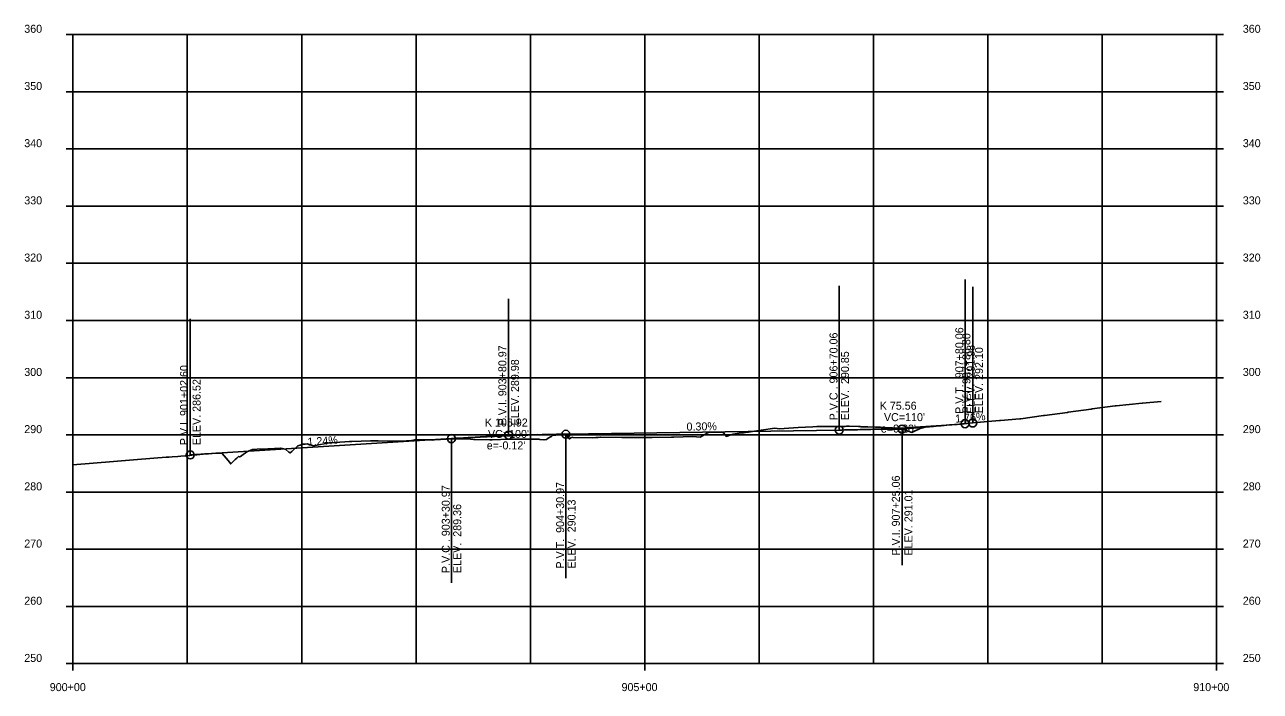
# Model space of a CAD drawing. Extents: x 1300404 to 1323571, y 234004 to 252077.
# Drawn here: x 1320996 to 1322076, y 238061 to 238644 of the extents above; entities that cross this region are included whole.
import ezdxf

# ---------------------------------------------------------------- set-up
doc = ezdxf.new("R2010")
doc.units = 0
for name, color, linetype in [('Default', 7, 'Continuous'), ('R_Axis', 7, 'Continuous'), ('R_Axis Annot', 7, 'Continuous'), ('R_Exist Surface', 7, 'Continuous'), ('R_Grid', 7, 'Continuous'), ('R_Vert Alg', 7, 'Continuous'), ('R_Vert Alg Annot', 7, 'Continuous')]:
    doc.layers.add(name, color=color, linetype=linetype)

msp = doc.modelspace()

# ---------------------------------------------------------------- linework, layer by layer
at = {"layer": 'R_Axis'}
for p, q in [((1321032.1, 238635.3), (1321038.1, 238635.3)), ((1321032.1, 238635.3), (1321038.1, 238635.3)), ((1321038.1, 238085.3), (1321038.1, 238635.3)), ((1322038.1, 238085.3), (1322038.1, 238635.3)), ((1322044.1, 238635.3), (1322038.1, 238635.3)), ((1322044.1, 238635.3), (1322038.1, 238635.3)), ((1321032.1, 238585.3), (1321038.1, 238585.3)), ((1322044.1, 238585.3), (1322038.1, 238585.3)), ((1321032.1, 238535.3), (1321038.1, 238535.3)), ((1322044.1, 238535.3), (1322038.1, 238535.3)), ((1321032.1, 238485.3), (1321038.1, 238485.3)), ((1322044.1, 238485.3), (1322038.1, 238485.3)), ((1321032.1, 238435.3), (1321038.1, 238435.3)), ((1322044.1, 238435.3), (1322038.1, 238435.3)), ((1321032.1, 238385.3), (1321038.1, 238385.3)), ((1322044.1, 238385.3), (1322038.1, 238385.3)), ((1321032.1, 238335.3), (1321038.1, 238335.3)), ((1322044.1, 238335.3), (1322038.1, 238335.3)), ((1321032.1, 238285.3), (1321038.1, 238285.3)), ((1322044.1, 238285.3), (1322038.1, 238285.3)), ((1321032.1, 238235.3), (1321038.1, 238235.3)), ((1322044.1, 238235.3), (1322038.1, 238235.3)), ((1321032.1, 238185.3), (1321038.1, 238185.3)), ((1322044.1, 238185.3), (1322038.1, 238185.3)), ((1321032.1, 238135.3), (1321038.1, 238135.3)), ((1322044.1, 238135.3), (1322038.1, 238135.3)), ((1321032.1, 238085.3), (1321038.1, 238085.3)), ((1321038.1, 238085.3), (1322038.1, 238085.3)), ((1321038.1, 238079.3), (1321038.1, 238085.3)), ((1321538.1, 238079.3), (1321538.1, 238085.3)), ((1322044.1, 238085.3), (1322038.1, 238085.3)), ((1322038.1, 238079.3), (1322038.1, 238085.3))]:
    msp.add_line(p, q, dxfattribs=at)
at = {"layer": 'R_Exist Surface'}
msp.add_lwpolyline([(1321038.1, 238259.2), (1321055.8, 238260.6), (1321073.4, 238262.1), (1321091.1, 238263.5), (1321108.7, 238265), (1321119.5, 238265.7), (1321119.8, 238265.7), (1321121.8, 238265.9), (1321124.8, 238266.1), (1321124.8, 238266.1), (1321124.8, 238266.1), (1321129.8, 238266.4), (1321129.9, 238266.4), (1321132.4, 238266.6), (1321132.4, 238266.6), (1321132.5, 238266.6), (1321136.1, 238266.9), (1321136.3, 238266.9), (1321136.3, 238266.9), (1321139.8, 238267.3), (1321140.1, 238267.3), (1321140.4, 238267.3), (1321142.1, 238267.5), (1321145.4, 238267.8), (1321146.4, 238267.9), (1321147.9, 238268.1), (1321148.9, 238268.2), (1321150.9, 238268.4), (1321150.9, 238268.4), (1321151.9, 238268.5), (1321153.5, 238268.6), (1321156.2, 238268.8), (1321156.7, 238268.8), (1321163.1, 238269.2), (1321165.5, 238269.3), (1321168.3, 238269.3), (1321168.5, 238269.3), (1321168.5, 238269.3), (1321168.6, 238269.1), (1321173.7, 238262.8), (1321176, 238259.9), (1321180, 238263.7), (1321181.4, 238264.8), (1321182.9, 238266.5), (1321183.8, 238266.1), (1321184.5, 238266.5), (1321190.1, 238270.4), (1321193.5, 238271.9), (1321194.6, 238272.3), (1321195.2, 238272.5), (1321196.1, 238272.6), (1321199.3, 238272.9), (1321208.4, 238273.2), (1321209.2, 238273.2), (1321219.2, 238273.7), (1321219.3, 238273.7), (1321219.3, 238273.7), (1321221.4, 238273.3), (1321223.7, 238272.7), (1321224.2, 238272.5), (1321226.8, 238270.2), (1321228, 238269.6), (1321229.6, 238270.9), (1321234.7, 238275.7), (1321236.7, 238276.2), (1321238.3, 238276.9), (1321239.1, 238277.3), (1321241.2, 238277.3), (1321242.8, 238277.4), (1321248.5, 238275.7), (1321251.6, 238276.4), (1321252.9, 238276.7), (1321259.6, 238277.9), (1321261.8, 238278.2), (1321264.1, 238278.3), (1321267.4, 238278.6), (1321279.8, 238279.6), (1321281.5, 238279.6), (1321282, 238279.6), (1321298.4, 238280), (1321304.5, 238280), (1321305, 238280), (1321323.2, 238279.7), (1321325.4, 238279.8), (1321334.1, 238280.3), (1321334.4, 238280.4), (1321337, 238281), (1321346.9, 238280.9), (1321347.5, 238280.9), (1321347.5, 238280.9), (1321347.6, 238280.9), (1321348, 238280.9), (1321350.7, 238281), (1321352.1, 238280.8), (1321353.4, 238280.9), (1321354.3, 238281.1), (1321370, 238281.9), (1321375.2, 238281.8), (1321385.7, 238281.5), (1321388.4, 238281.2), (1321389.9, 238281.4), (1321402.7, 238281.1), (1321403.2, 238281.1), (1321403.8, 238281.1), (1321404.6, 238281), (1321419.6, 238281.6), (1321421.7, 238281.6), (1321433.5, 238281.6), (1321433.8, 238281.6), (1321445.5, 238281.6), (1321446.4, 238281.4), (1321450, 238280.9), (1321452.3, 238281.3), (1321453.6, 238282.5), (1321455.6, 238283.7), (1321456.1, 238283.7), (1321456.3, 238283.7), (1321457.3, 238284.8), (1321466.2, 238285.5), (1321469.8, 238285.4), (1321470.9, 238283.7), (1321472.3, 238281.7), (1321473.5, 238282.7), (1321475.3, 238283.2), (1321475.5, 238283.1), (1321475.6, 238283.1), (1321492.7, 238282.8), (1321495.2, 238283), (1321497.3, 238282.9), (1321499.4, 238283.3), (1321518.1, 238283.1), (1321520.5, 238283.1), (1321522.8, 238283.1), (1321542, 238282.9), (1321544.5, 238283), (1321561.4, 238283.3), (1321563.5, 238283.4), (1321579.9, 238283.8), (1321583.3, 238283.7), (1321586.7, 238283.4), (1321592.6, 238286.7), (1321593.1, 238287.1), (1321594.1, 238287.5), (1321594.1, 238287.4), (1321594.5, 238287.6), (1321595.7, 238287.6), (1321606.5, 238287.5), (1321607, 238287.1), (1321609.6, 238283.9), (1321613.1, 238285.2), (1321615.4, 238286), (1321620.6, 238286.8), (1321622.3, 238287), (1321624.4, 238287.2), (1321626.1, 238287.4), (1321628.9, 238287.7), (1321634, 238288.4), (1321649.9, 238290.9), (1321651.8, 238291.2), (1321655.9, 238290.7), (1321668.2, 238291.4), (1321672.4, 238291.7), (1321685.1, 238292.4), (1321688.7, 238292.7), (1321699.7, 238292.6), (1321709, 238292.6), (1321711.1, 238292.7), (1321713.3, 238292.7), (1321714.7, 238293), (1321717, 238292.9), (1321725.1, 238292.6), (1321726.8, 238292.6), (1321727.2, 238292.4), (1321729.2, 238292.4), (1321733.1, 238292.2), (1321739.9, 238292), (1321741.2, 238291.9), (1321744.2, 238291.9), (1321746.8, 238291.8), (1321749.2, 238291.6), (1321753, 238291.5), (1321757.2, 238291.3), (1321761.7, 238291.2), (1321762.1, 238291), (1321762.7, 238290.9), (1321765.3, 238289.8), (1321771.8, 238287.4), (1321773.3, 238288.2), (1321779.1, 238290.9), (1321781.3, 238291.5), (1321781.4, 238291.6), (1321783.5, 238292.2), (1321784.7, 238292.3), (1321785, 238292.3), (1321787.9, 238292.6), (1321788.7, 238292.6), (1321789.4, 238292.7), (1321793, 238293), (1321796.2, 238293.2), (1321797.4, 238293.3), (1321801.7, 238293.7), (1321805.5, 238294), (1321813.5, 238294.7), (1321814.2, 238294.8), (1321814.8, 238294.8), (1321820.1, 238295.3), (1321821.6, 238295.4), (1321831.3, 238296.3), (1321831.6, 238296.3), (1321848.4, 238297.8), (1321848.8, 238297.8), (1321849.3, 238297.9), (1321866.1, 238299.3), (1321866.9, 238299.4), (1321886.9, 238302.2), (1321887.7, 238302.3), (1321907.8, 238305), (1321908.5, 238305.1), (1321928.6, 238307.9), (1321929.4, 238308), (1321949.5, 238310.8), (1321950.3, 238310.8), (1321973.1, 238313), (1321973.4, 238313.1), (1321989.7, 238314.6)], dxfattribs=at)
at = {"layer": 'R_Grid'}
for p, q in [((1321038.1, 238635.3), (1322038.1, 238635.3)), ((1321038.1, 238635.3), (1322038.1, 238635.3)), ((1321138.1, 238085.3), (1321138.1, 238635.3)), ((1321238.1, 238085.3), (1321238.1, 238635.3)), ((1321338.1, 238085.3), (1321338.1, 238635.3)), ((1321438.1, 238085.3), (1321438.1, 238635.3)), ((1321538.1, 238085.3), (1321538.1, 238635.3)), ((1321638.1, 238085.3), (1321638.1, 238635.3)), ((1321738.1, 238085.3), (1321738.1, 238635.3)), ((1321838.1, 238085.3), (1321838.1, 238635.3)), ((1321938.1, 238085.3), (1321938.1, 238635.3)), ((1321038.1, 238585.3), (1322038.1, 238585.3)), ((1321038.1, 238535.3), (1322038.1, 238535.3)), ((1321038.1, 238485.3), (1322038.1, 238485.3)), ((1321038.1, 238435.3), (1322038.1, 238435.3)), ((1321038.1, 238385.3), (1322038.1, 238385.3)), ((1321038.1, 238335.3), (1322038.1, 238335.3)), ((1321038.1, 238285.3), (1322038.1, 238285.3)), ((1321038.1, 238235.3), (1322038.1, 238235.3)), ((1321038.1, 238185.3), (1322038.1, 238185.3)), ((1321038.1, 238135.3), (1322038.1, 238135.3))]:
    msp.add_line(p, q, dxfattribs=at)
at = {"layer": 'R_Vert Alg'}
for p, q in [((1321708.2, 238289.5), (1321708.2, 238415.5)), ((1321818.2, 238295.1), (1321818.2, 238421.1)), ((1321824.9, 238295.7), (1321824.9, 238414.7)), ((1321419.1, 238285.1), (1321419.1, 238404.1)), ((1321140.7, 238267.8), (1321140.7, 238386.8)), ((1321818.2, 238295.1), (1321824.9, 238295.7)), ((1321394.1, 238283.6), (1321419.1, 238285.1)), ((1321419.1, 238285.1), (1321444.1, 238285.5)), ((1321469.1, 238285.9), (1321708.2, 238289.5)), ((1321469.1, 238285.9), (1321469.1, 238159.9)), ((1321735.7, 238289.9), (1321763.2, 238290.3)), ((1321763.2, 238290.3), (1321790.7, 238292.7)), ((1321763.2, 238290.3), (1321763.2, 238171.3)), ((1321140.7, 238267.8), (1321369.1, 238282)), ((1321369.1, 238282), (1321369.1, 238156))]:
    msp.add_line(p, q, dxfattribs=at)
for points in [[(1321369.1, 238282), (1321371.2, 238282.2), (1321373.3, 238282.3), (1321375.4, 238282.4), (1321377.4, 238282.5), (1321379.5, 238282.7), (1321381.6, 238282.8), (1321383.7, 238282.9), (1321385.8, 238283), (1321387.9, 238283.1), (1321389.9, 238283.2), (1321392, 238283.3), (1321394.1, 238283.4), (1321396.2, 238283.5), (1321398.3, 238283.6), (1321400.4, 238283.7), (1321402.4, 238283.8), (1321404.5, 238283.9), (1321406.6, 238284), (1321408.7, 238284.1), (1321410.8, 238284.2), (1321412.9, 238284.3), (1321414.9, 238284.4), (1321417, 238284.5), (1321421.2, 238284.6), (1321423.3, 238284.7), (1321425.4, 238284.8), (1321427.4, 238284.9), (1321429.5, 238284.9), (1321431.6, 238285), (1321433.7, 238285.1), (1321435.8, 238285.1), (1321437.9, 238285.2), (1321439.9, 238285.3), (1321442, 238285.3), (1321444.1, 238285.4), (1321446.2, 238285.4), (1321448.3, 238285.5), (1321450.4, 238285.5), (1321452.4, 238285.6), (1321454.5, 238285.6), (1321456.6, 238285.7), (1321458.7, 238285.7), (1321460.8, 238285.8), (1321462.9, 238285.8), (1321464.9, 238285.8), (1321467, 238285.9), (1321469.1, 238285.9)], [(1321708.2, 238289.5), (1321710.5, 238289.5), (1321712.8, 238289.6), (1321715.1, 238289.6), (1321717.4, 238289.6), (1321719.7, 238289.7), (1321722, 238289.7), (1321724.2, 238289.8), (1321726.5, 238289.9), (1321728.8, 238289.9), (1321731.1, 238290), (1321733.4, 238290.1), (1321735.7, 238290.1), (1321738, 238290.2), (1321740.3, 238290.3), (1321742.6, 238290.4), (1321744.9, 238290.5), (1321747.2, 238290.6), (1321749.5, 238290.7), (1321751.7, 238290.8), (1321754, 238290.9), (1321756.3, 238291), (1321758.6, 238291.1), (1321760.9, 238291.2), (1321765.5, 238291.4), (1321767.8, 238291.5), (1321770.1, 238291.7), (1321772.4, 238291.8), (1321774.7, 238291.9), (1321777, 238292.1), (1321779.2, 238292.2), (1321781.5, 238292.4), (1321783.8, 238292.5), (1321786.1, 238292.7), (1321788.4, 238292.8), (1321790.7, 238293), (1321793, 238293.1), (1321795.3, 238293.3), (1321797.6, 238293.5), (1321799.9, 238293.6), (1321802.2, 238293.8), (1321804.5, 238294), (1321806.7, 238294.2), (1321809, 238294.4), (1321811.3, 238294.5), (1321813.6, 238294.7), (1321815.9, 238294.9), (1321818.2, 238295.1)]]:
    msp.add_lwpolyline(points, dxfattribs=at)
for centre in [(1321818.2, 238295.1), (1321824.9, 238295.7), (1321369.1, 238282), (1321419.1, 238285.1), (1321469.1, 238285.9), (1321708.2, 238289.5), (1321763.2, 238290.3), (1321140.7, 238267.8)]:
    msp.add_circle(centre, 3.5, dxfattribs=at)

# ---------------------------------------------------------------- texts
at = {"layer": 'Default'}
msp.add_text('-', height=0.0001, dxfattribs=at).set_placement((1321038.1, 238085.3))
at = {"layer": 'R_Axis Annot'}
for s, p in [('360', (1320995.5, 238636.8)), ('360', (1320995.5, 238636.8)), ('360', (1322061.1, 238636.8)), ('360', (1322061.1, 238636.8)), ('350', (1320995.5, 238586.8)), ('350', (1322061.1, 238586.8)), ('340', (1320995.5, 238536.8)), ('340', (1322061.1, 238536.8)), ('330', (1320995.5, 238486.8)), ('330', (1322061.1, 238486.8)), ('320', (1320995.5, 238436.8)), ('320', (1322061.1, 238436.8)), ('310', (1320995.5, 238386.8)), ('310', (1322061.1, 238386.8)), ('300', (1320995.5, 238336.8)), ('300', (1322061.1, 238336.8)), ('290', (1320995.5, 238286.8)), ('290', (1322061.1, 238286.8)), ('280', (1320995.5, 238236.8)), ('280', (1322061.1, 238236.8)), ('270', (1320995.5, 238186.8)), ('270', (1322061.1, 238186.8)), ('260', (1320995.5, 238136.8)), ('260', (1322061.1, 238136.8)), ('250', (1320995.5, 238086.8)), ('250', (1322061.1, 238086.8)), ('900+00', (1321017.8, 238061.3)), ('905+00', (1321517.8, 238061.3)), ('910+00', (1322017.8, 238061.3))]:
    msp.add_text(s, height=7, dxfattribs=at).set_placement(p)
at = {"layer": 'R_Vert Alg Annot'}
for s, rotation, p in [('P.V.C . 906+70.06', 90, (1321706.7, 238298)), ('P.V.T.  907+80.06', 90, (1321816.7, 238303.6)), ('P.V.I. 907+86.80', 90, (1321822.9, 238304.2)), ('P.V.I. 903+80.97', 90, (1321417.1, 238293.6)), ('ELEV.  291.98', 90, (1321826.7, 238303.6)), ('ELEV. 292.10', 90, (1321833.9, 238304.2)), ('ELEV. 289.98', 90, (1321428.1, 238293.6)), ('ELEV.  290.85', 90, (1321716.7, 238298)), ('P.V.I. 901+02.60', 90, (1321138.7, 238276.3)), ('ELEV. 286.52', 90, (1321149.7, 238276.3)), ('0.30%', 0.8594, (1321574.7, 238289)), ('1.76%', 5.0173, (1321809.9, 238295.9)), ('1.24%', 3.5595, (1321243.4, 238275.7)), ('P.V.T.  904+30.97', 90, (1321467.6, 238168.4)), ('P.V.I. 907+25.06', 90, (1321761.2, 238179.8)), ('P.V.C . 903+30.97', 90, (1321367.6, 238164.5)), ('ELEV. 291.01', 90, (1321772.2, 238179.8)), ('ELEV.  289.36', 90, (1321377.6, 238164.5)), ('ELEV.  290.13', 90, (1321477.6, 238168.4))]:
    msp.add_text(s, height=7, rotation=rotation, dxfattribs=at).set_placement(p)
for s, p in [('K 75.56', (1321743.6, 238307.3)), ('K 105.92', (1321398.3, 238292.6)), ("VC=110'", (1321747.3, 238297.3)), ("VC=100'", (1321401, 238282.6)), ("e=0.20'", (1321744.6, 238287.3)), ("e=-0.12'", (1321399.9, 238272.6))]:
    msp.add_text(s, height=7, dxfattribs=at).set_placement(p)

doc.saveas('drawing.dxf')
